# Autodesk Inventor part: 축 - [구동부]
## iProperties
Company: 한국ATC센터
Created: 2014-08
Part Number: 축 - [구동부]
Document SubType Name: Modeling
Designer: KYOUNG IL JANG
Density: 7.86 g/cm^3
Material: 강, 연강
Mass: 427.955 g
Surface Area: 136.701 cm^2
Volume: 54.4472 cm^3
Author: KYOUNG IL JANG
